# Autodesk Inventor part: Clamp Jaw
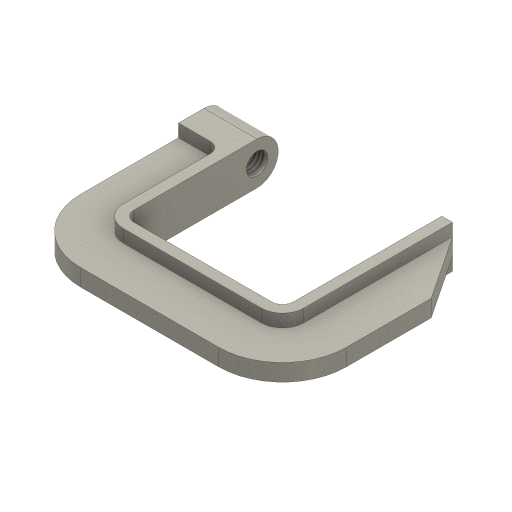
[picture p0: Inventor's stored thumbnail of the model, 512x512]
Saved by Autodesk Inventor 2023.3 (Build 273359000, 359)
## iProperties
Created: 2020-10
Part Number: Clamp Jaw
Material: Iron, Cast
Document SubType Name: Modeling
Designer: User
Density: 7.15 g/cm^3
Appearance: Acciaio - Fuso
Author: User
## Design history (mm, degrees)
sketch "Sketch1"
  geometry: L1 (0, 30)-(0, 98); L2 (0, 98)-(25, 98); L3 (25, 98)-(25, 30); L4 (30, 25)-(95, 25); L5 (100, 30)-(100, 100); L6 (100, 100)-(125, 100); L7 (125, 100)-(125, 30); L8 (95, 0)-(30, 0); L9 (0, 76)-(15, 76); L10 (20, 71)-(20, 30); L11 (30, 20)-(95, 20); L12 (105, 30)-(105, 100); L13 (105, 100)-(125, 70); A1 r 5 centre (30, 30) between (25, 30) and (30, 25); A2 r 5 centre (95, 30) between (95, 25) and (100, 30); A3 r 5 centre (15, 71) between (20, 71) and (15, 76); A4 r 10 centre (30, 30) between (20, 30) and (30, 20); A5 r 10 centre (95, 30) between (95, 20) and (105, 30); A6 r 30 centre (30, 30) between (0, 30) and (30, 0); A7 r 30 centre (95, 30) between (95, 0) and (125, 30); 7 further points
  constraints: 26 end point, 17 point on line, 14 point on circle, 14 tangent, 7 centre point, 6 perpendicular, 3 equal radius, 2 horizontal, 2 vertical
  dimensions: "d0" = 98 distance of point (0, 0) L1.end; "d1" = 25 distance of L1.end L2.end; "d2" = 73 distance of L2.end point (25, 25); "d3" = 75 distance of point (25, 25) point (100, 25); "d4" = 75 distance of point (100, 25) L5.end; "d5" = 25 distance of L5.end L6.end; "d6" = 100 distance of L6.end point (125, 0); "d7" = 20 distance of L9.start point (20, 76); "d8" = 22 distance between parallel lines of L2 L9; "d9" = 56 distance of point (20, 76) point (20, 20); "d10" = 85 distance of point (20, 20) point (105, 20); "d11" = 80 distance of point (105, 20) L12.end; "d12" = 30 distance from line of L6 L13.end; "d13" = 5 radius of A1; "d14" = 10 radius of A4; "d15" = 30 radius of A6; "d16" = 30 radius of A7
extrude "Extrusion1" new body sketch "Sketch1" stored distance "d17" = 8; taper "d18" = 0 deg
extrude "Extrusion2" join sketch "Sketch1" stored distance "d19" = 20; taper "d20" = 0 deg
fillet "Fillet1" dims "d21" = 10
sketch "Schizzo2"
  geometry: A1 r 10 centre (4, 58) between (14, 58) and (-6, 58) reference; 2 further points
  constraints: 1 coincident
hole "Foro2" sketch "Schizzo2" at (4, 58) diameter "d35" = 10.106; stored, may be unused: countersink angle "d39" = 90 deg, drill point angle "d41" = 118 deg; dims "d36" = 24, "d37" = 4, "d38" = 2, "d40" = 32.3
body "Solid1"
